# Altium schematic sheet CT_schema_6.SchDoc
size 278 x 170 mm
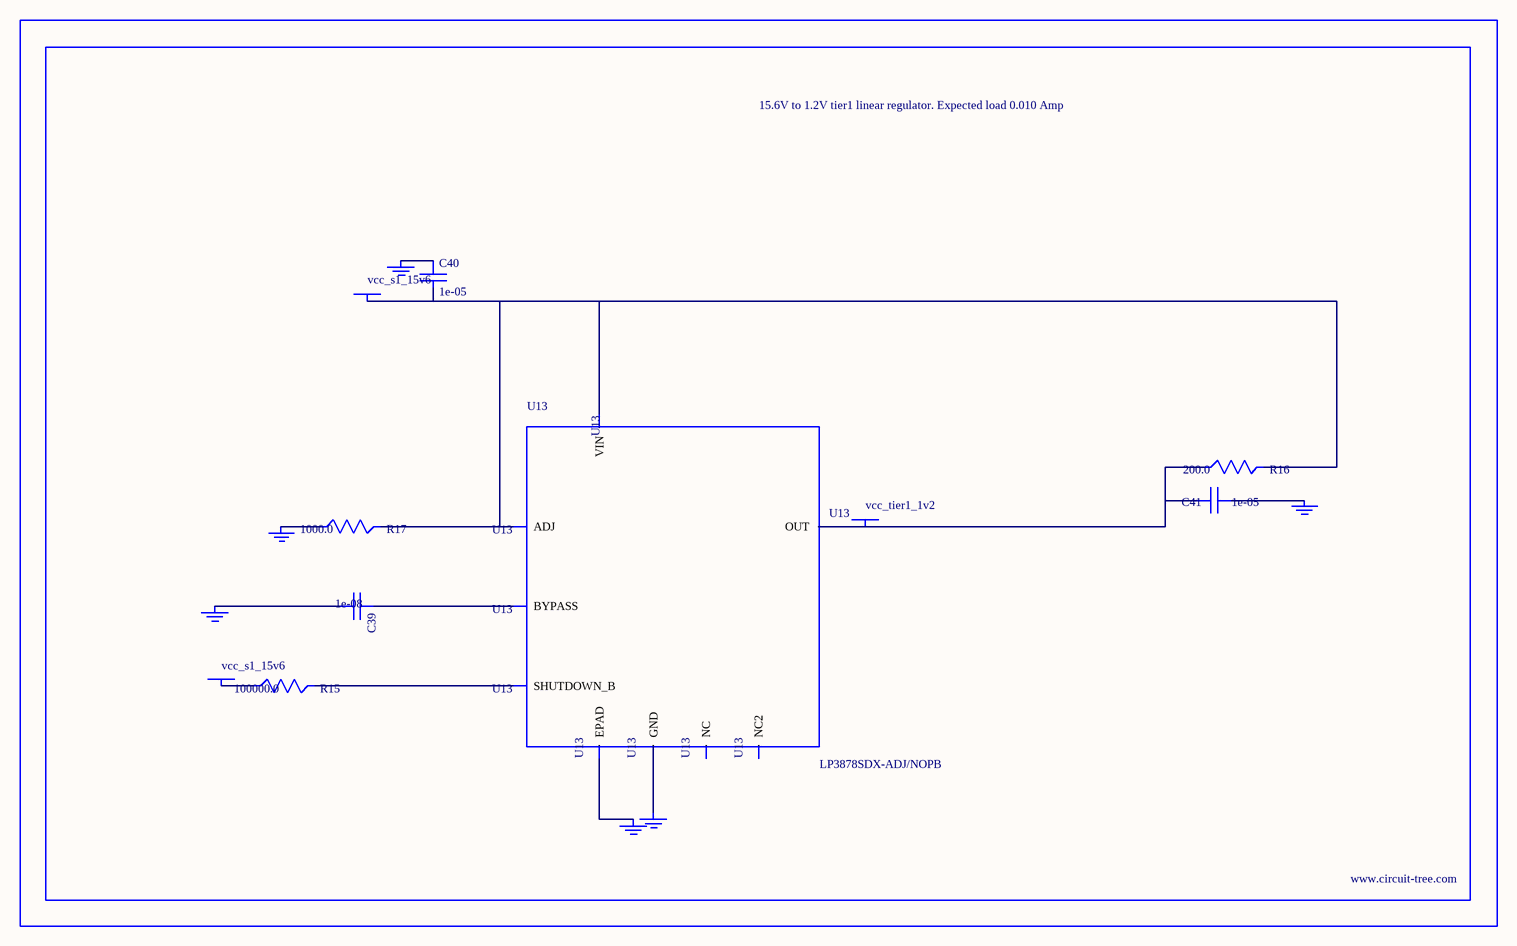
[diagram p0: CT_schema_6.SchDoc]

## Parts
BORDER5  (no value)
C39  1e-08  [C0402]
C40  1e-05  [C1210]
C41  1e-05  [C0805]
GND_INSTANCE_5_0  (no value)
GND_INSTANCE_5_1  (no value)
GND_INSTANCE_5_2  (no value)
GND_INSTANCE_5_3  (no value)
GND_INSTANCE_5_4  (no value)
GND_INSTANCE_5_5  (no value)
POWER_INSTANCE_5_0  vcc_s1_15v6
POWER_INSTANCE_5_1  vcc_s1_15v6
POWER_INSTANCE_5_2  vcc_tier1_1v2
R15  100000.0  [R0603]
R16  200.0  [R0603]
R17  1000.0  [R0603]
U13  LP3878SDX-ADJ/NOPB  [WSON-8]

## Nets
NetC39_1: C39.1 U13.1(BYPASS)
NetC39_2: C39.2 GND_INSTANCE_5_0.0(GND)
NetC40_1: C40.1 GND_INSTANCE_5_1.0(GND)
NetC40_2: C40.2 POWER_INSTANCE_5_0.0(PWR) R16.2 R17.2 U13.4(VIN) U13.6(ADJ)
NetC41_1: C41.1 GND_INSTANCE_5_2.0(GND)
NetC41_2: C41.2 POWER_INSTANCE_5_2.0(PWR) R16.1 U13.5(OUT)
NetGND_INSTANCE_5_3_0: GND_INSTANCE_5_3.0(GND) R17.1
NetGND_INSTANCE_5_4_0: GND_INSTANCE_5_4.0(GND) U13.PAD(EPAD)
NetGND_INSTANCE_5_5_0: GND_INSTANCE_5_5.0(GND) U13.3(GND)
NetPOWER_INSTANCE_5_1_0: POWER_INSTANCE_5_1.0(PWR) R15.1
NetR15_2: R15.2 U13.8(SHUTDOWN_B)

Not connected (* = marked no-connect by the designer): U13 2(NC) 7(NC2)

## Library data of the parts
BORDER5 = BORDER_PAGE5
C39 = C0402C103K3RAC
C40 = C1210C106K5PACTU
C41 = GRM219R60J106ME19D
GND_INSTANCE_5_0-GND_INSTANCE_5_5 = GND
POWER_INSTANCE_5_0-POWER_INSTANCE_5_2 = PWR
R15 = RC0603JR-07100KL
R16 = RC0603JR-07200RL
R17 = RC0603JR-071KL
